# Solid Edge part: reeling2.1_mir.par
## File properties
Last saved by: Mac
Revision: 52
Accuracy: 0,990
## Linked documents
reeling2.1.par
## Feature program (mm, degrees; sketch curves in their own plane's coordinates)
part copy "CopiedPart_1"
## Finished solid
Body 1: solid body, 49 faces, 67 edges, 26 vertices.
  Faces by surface: cylinder 18, plane 18, spline 8, torus 5
  Edges by curve: intersection 33, circle 28, curve on surface 2, ellipse 2, line 2
Bounding box of the edges (mm; curved faces can reach further): 167.489 x 29.926 x 16.651, from (-128.7931, -10.733, 1.6772) to (38.6964, 19.1935, 18.3277).
Cylindrical faces by radius (mm): R0.1 x11, R0.8 x7
Toroidal faces (ring radius, tube radius in mm): R0.5971 r0.1 x1, R0.6616 r0.1 x1, R0.9337 r0.1 x1, R1.0266 r0.1 x1, R1.2594 r0.1 x1
Planar faces by outward normal: +z 1, -z 1, oblique 16
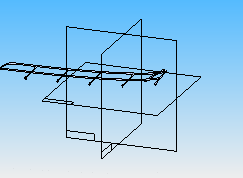
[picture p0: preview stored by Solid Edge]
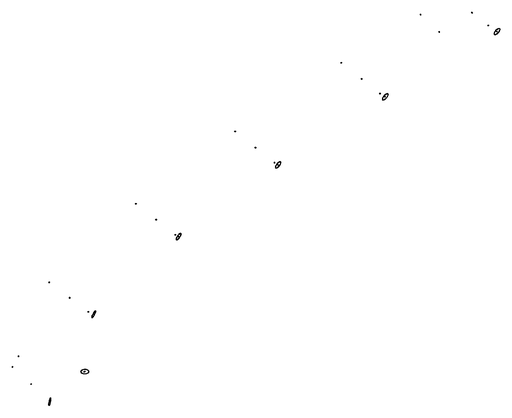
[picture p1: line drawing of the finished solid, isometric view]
